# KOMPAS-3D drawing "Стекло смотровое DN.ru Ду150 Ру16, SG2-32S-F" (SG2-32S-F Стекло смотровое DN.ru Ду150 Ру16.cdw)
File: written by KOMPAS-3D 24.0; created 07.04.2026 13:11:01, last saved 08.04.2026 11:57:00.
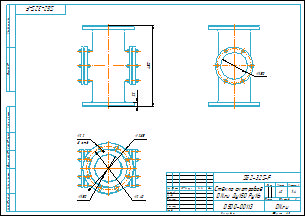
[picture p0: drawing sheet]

Document properties: Автор: Main; Форматы листов документа: A3; Полное имя файла: SG2-32S-F Стекло смотровое DN.ru Ду150 Ру16.m3d; Масса: 42; Наименование: Стекло смотровое DN.ru Ду150 Ру16; Количество листов документа: 1; Примечание: D500-00113

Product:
- Body: Тело 1  | qty 1
    Масса: 46.781742
- Part/product: Стекло смотровое DN.ru Ду150 Ру16  | designation SG2-32S-F
    Масса: 42
    Раздел спецификации: Прочие изделия
    Примечание: D500-00113

Views: Вид 1, Снизу, Проекционный вид 2
Referenced files in D:\DN.ru Аутсерс\Стекло смотровое DN.ru\Стекло смотровое DN.ru SG2-34G-F тип В ГОСТ 21836-2021 Ду100 Ру16, углеродистая сталь, фланцевое\: SG2-34G-F тип В Стекло смотровое DN.ru Ду100 Ру16.m3d, SG2-34G-F тип ВСтекло смотровое DN.ru Ду100 Ру16.cdw
Referenced files in D:\DN.ru Аутсерс\Стекло смотровое DN.ru\SG2-32S-F Стекло смотровое DN.ru Ду150 Ру16\: SG2-32S-F Стекло смотровое DN.ru Ду150 Ру16.m3d
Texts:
  SG2-32S-F
  Стекло смотровое
  DN.ru Ду150 Ру16
  Стекло смотровое DN.ru Ду150 Ру16
  SG2-32S-F Стекло смотровое DN.ru Ду150 Ру16
Dimensions and other numbers on the sheet: 0; 3; 2; 4; 450; 22; 285; 240; 150; 8 отв.; 1:4; 1; 42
